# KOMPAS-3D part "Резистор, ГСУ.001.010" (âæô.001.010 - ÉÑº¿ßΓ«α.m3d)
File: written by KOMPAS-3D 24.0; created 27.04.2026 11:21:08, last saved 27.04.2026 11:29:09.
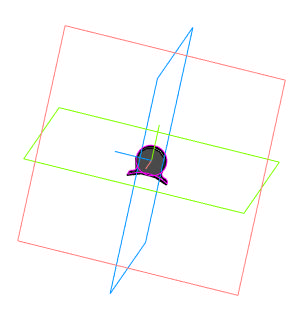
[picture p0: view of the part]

Document properties: Автор: USG_411; Полное имя файла: C:\Users\USG_411\Desktop\ГМ2704_411-15\Двигатель мясорубки\ГСУ.001.010 - Резистор.m3d

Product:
- Part/product: Резистор  | designation ГСУ.001.010
    Масса: 0.000471

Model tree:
1. Эскиз:1
2. Элемент выдавливания:1
     Расстояние 1 = 1.5
3. Скругление:1  (with: Грань.Элемент выдавливания:1)
     Радиус = 0.3

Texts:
  ГСУ.001.010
